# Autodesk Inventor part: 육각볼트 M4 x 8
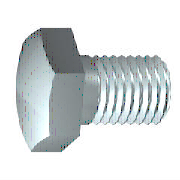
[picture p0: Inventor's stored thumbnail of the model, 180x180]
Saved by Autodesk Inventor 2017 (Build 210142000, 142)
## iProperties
Created: 2012-02
Part Number: 육각볼트 M4 x 8
Material: 강철, 연강
Description: 6각 머리 나사
Document SubType Name: Modeling
Standard: ISO 4017
Designer: mduedu
Standard Revision: Third edition 1999-08-15
Standards Organization: ISO
Language: ko-KR
Size Designation: M4 x 10
Categories: <MemberInstance><Categories><Category DisplayName="조임쇠" InternalName="e4da775c-781d-43d5-af7c-5136215cf5a6" Mnemonic="FSTN"><Category DisplayName="볼트" InternalN
Density: 7.86 g/cm^3
Appearance: 반광택
IsCustomPart: 0
Author: mduedu
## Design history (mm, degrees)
sketch "스케치1"
  geometry: L1 (0, 3.015)-(0, 2); L2 (1.75, 2)-(8, 2); L3 (8, 2)-(8, 0); L4 (8, 0)-(-0.4, 0); L5 (-2.08, 0)-(9.68, 0) reference; L6 (-0.4, 0)-(-0.4, 3.015); L7 (-0.4, 3.015)-(0, 3.015); L8 (1.75, 2)-(1.32, 2); L9 (1.32, 2)-(0, 2); L10 (0, -0.603)-(0, 3.618) reference
  constraints: 16 end point, 2 collinear, 2 perpendicular, 1 parallel
  dimensions: "d0" = 8 distance between parallel lines of L3 L1 (= NLG); "d1" = 6.25 distance from line of L2.start L3 (= GEL); "d2" = 4 diameter of L2 L4 (= GD); "d9" = 0.4001 distance between parallel lines of L6 L1 (computed from SD); "d10" = 6.03 diameter of L7 L4 (= SD2); "d13" = 0.42952 distance of L2.start L8.end (computed from GAL); "d14" = 4 diameter of L9 L4 (= BDM)
revolve "본체" sketch "스케치1" stored, may be unused: angle "d12" = 90 deg
sketch "스케치2"
  geometry: L1 (0, 4.041)-(3.5, 2.021); L2 (3.5, 2.021)-(3.5, -2.021); L3 (3.5, -2.021)-(0, -4.041); L4 (0, -4.041)-(-3.5, -2.021); L5 (-3.5, -2.021)-(-3.5, 2.021); L6 (-3.5, 2.021)-(0, 4.041); 2 further points
  constraints: 12 end point, 1 coincident, 1 vertical, 11 other
  dimensions: "d11" = 7 distance between parallel lines of L5 L2 (= SW)
extrude "머리" join sketch "스케치2" distance "d3" = 2.4 (= KOH - SD); taper "d4" = 0 deg
sketch "스케치4"
  geometry: L1 (-2.8, 3.5)-(-2.8, 4.041); L2 (-2.8, 4.041)-(-2.487, 4.041); L3 (-2.487, 4.041)-(-2.8, 3.5); L4 (-3.28, 0)-(0.08, 0) reference; L5 (-0.4, 4.041)-(-2.8, 4.041) reference; L6 (-2.8, 2.021)-(-2.8, 4.041) reference
  constraints: 6 end point, 2 collinear, 1 perpendicular, 1 vertical
  dimensions: "d5" = 30 deg angle of L3 L1 (= ANG1); "d19" = 7 diameter of L1.start L4 (= SW0)
revolve "모따기1" sketch "스케치4" stored, may be unused: angle "d21" = 90 deg
workplane "Work Plane1"
body "Solid1"
feature "스레드" dims "d15" = 6.25 (= GEL), "d16" = 0
chamfer "모따기2" distance "d6" = 0.42941 (= -0.5 x SPD + 0.5 x GD); stored, may be unused: second distance "d7" = 0.42952 (computed from GUL), angle "d55" = 45 deg
other parameters: "NLG" = 8 [user parameter; used in 1 equation term], "GD" = 4 (= NND) [user parameter; used in 2 equation terms], "BDM" = 4 (= NND) [user parameter; used in 1 equation term], "KOH" = 2.8 [user parameter; used in 1 equation term], "GEL" = 6.25 [user parameter; used in 2 equation terms], "SW" = 7 [user parameter; used in 2 equation terms], "SW0" = 7 (= SW) [user parameter; used in 1 equation term], "SPD" = 3.14117 (= NND - 1.2269 x PTC) [user parameter; used in 1 equation term], "SD2" = 6.03 [user parameter; used in 2 equation terms], "SD" = 0.4 [user parameter; used in 2 equation terms], "ANG1" = 30 deg [user parameter; used in 1 equation term], "GAL" = 0.42941 (= 0.61345 x PTC) [user parameter; used in 1 equation term], "GUL" = 0.42941 (= 0.61345 x PTC) [user parameter; used in 1 equation term], "d8" = 0, "RR" = 0.2 [user parameter], "d57" = 0, "d58" = 0, "TPU" = 14.28571 (computed from PTC) [user parameter], "GD1" = 3.14117 (= THREADDIA - 1.2269 x PTC) [user parameter], "THREADDIA" = 4 [user parameter; used in 1 equation term], "SDH" = 6.03 (= SD2) [user parameter], "SDHG" = 2.1 [user parameter], "TOA" = 30 deg [user parameter], "PTC" = 0.7 [user parameter; used in 5 equation terms], "NND" = 4 [user parameter; used in 3 equation terms], "E0" = 8.085 [user parameter]
